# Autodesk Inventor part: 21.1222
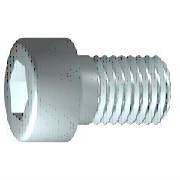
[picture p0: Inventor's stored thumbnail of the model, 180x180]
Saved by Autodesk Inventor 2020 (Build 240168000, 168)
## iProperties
Created: 2006-02
Part Number: 21.1222
Material: Steel, Mild
Description: M5 X 20 SHCS
Document SubType Name: Modeling
Standard: DIN 7984
Designer: Andy Moles
Standards Organization: DIN
Language: en-US
Size Designation: M5 x 20
Categories: <MemberInstance><Categories><Category DisplayName="Fasteners" InternalName="e4da775c-781d-43d5-af7c-5136215cf5a6" Mnemonic="FSTN"><Category DisplayName="Bolts"
Density: 7.85 g/cm^3
Mass: 4.42774 g
Surface Area: 5.40621 cm^2
Volume: 0.564044 cm^3
Appearance: Zinc
Author: Andy Moles
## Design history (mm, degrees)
sketch "Sketch1"
  geometry: L1 (0.2, 0)-(20, 0); L2 (20, 0)-(20, 2.5); L3 (20, 2.5)-(2.4, 2.5); L4 (2.4, 2.5)-(1.909, 2.5); L5 (1.909, 2.5)-(0, 2.5); L6 (0, 2.5)-(0, 4.25); L7 (0, 4.25)-(-3.5, 4.25); L8 (-3.5, 4.25)-(-3.5, 1.732); L9 (-3.5, 1.732)-(-0.8, 1.732); L10 (-0.8, 1.732)-(0.2, 0); L11 (-5.85, 0)-(27.05, 0) reference; L12 (0, -0.425)-(0, 5.525) reference; L13 (2.4, 2.5)-(0, 2.5)
  constraints: 22 end point, 6 parallel, 2 collinear, 2 perpendicular, 1 horizontal, 1 point on line
  dimensions: "d1" = 17.6 distance from line of L3.end L2 (= GEL); "d2" = 0.49086 distance of L4.end L3.end (computed from GAL); "d3" = 3.5 distance between parallel lines of L8 L6 (= KOH); "d4" = 2.7 distance of L8.end L9.end (= INTI); "d5" = 60 deg angle of L10 L1; "d6" = 5 diameter of L3 L1 (= GD); "d7" = 5 diameter of L5 L1 (= BDM); "d8" = 3.4641 diameter of L9 L1 (= 1.1547 x SW); "d9" = 8.5 diameter of L7 L1 (= KOD); "d26" = 20 distance between parallel lines of L12 L2 (= NLG)
revolve "Body" sketch "Sketch1" stored, may be unused: angle "d10" = 90 deg
sketch "Sketch2"
  geometry: L1 (0, -5.1)-(0, 6.8) reference; L2 (-5.1, 0)-(6.8, 0) reference; L3 (1.732, 0)-(0.866, -1.5); L4 (0.866, -1.5)-(-0.866, -1.5); L5 (-0.866, -1.5)-(-1.732, 0); L6 (-1.732, 0)-(-0.866, 1.5); L7 (-0.866, 1.5)-(0.866, 1.5); L8 (0.866, 1.5)-(1.732, 0); 2 further points
  constraints: 12 end point, 1 coincident, 1 horizontal alignment, 1 point on line, 12 other
extrude "Slot" join sketch "Sketch2" stored distance "d11" = 10; taper "d12" = 0 deg
workplane "Work Plane1"
body "Solid1"
fillet "Fillet1" dims "d17" = 0.5 (= RR)
feature "Thread" dims "d13" = 20, "d14" = 0
chamfer "Chamfer1" distance "d15" = 0.49076 (= -0.5 x SPD + 0.5 x GD); stored, may be unused: second distance "d16" = 0.49076 (= GUL), angle "d27" = 45 deg
other parameters: "GD" = 5 (= NND) [user parameter; used in 2 equation terms], "NLG" = 20 [user parameter; used in 1 equation term], "GEL" = 17.6 [user parameter; used in 1 equation term], "KOD" = 8.5 [user parameter; used in 1 equation term], "KOH" = 3.5 [user parameter; used in 1 equation term], "INTI" = 2.7 [user parameter; used in 1 equation term], "GAL" = 0.49076 (= 0.61345 x PTC) [user parameter; used in 1 equation term], "GUL" = 0.49076 (= 0.61345 x PTC) [user parameter; used in 1 equation term], "BDM" = 5 (= NND) [user parameter; used in 1 equation term], "SW" = 3 [user parameter; used in 2 equation terms], "RR" = 0.5 [user parameter; used in 1 equation term], "SPD" = 4.01848 (= NND - 1.2269 x PTC) [user parameter; used in 1 equation term], "d19" = 0, "d28" = 0, "d29" = 0, "TOA" = 30 deg [user parameter], "GD1" = 4.01848 (= THREADDIA - 1.2269 x PTC) [user parameter], "THREADDIA" = 5 [user parameter; used in 1 equation term], "FAWI" = 45 deg [user parameter], "ANG" = 120 deg [user parameter], "TPU" = 12.5 (computed from PTC) [user parameter], "PTC" = 0.8 [user parameter; used in 5 equation terms], "NND" = 5 [user parameter; used in 3 equation terms], "E0" = 3.465 (= 1.155 x SW) [user parameter]
